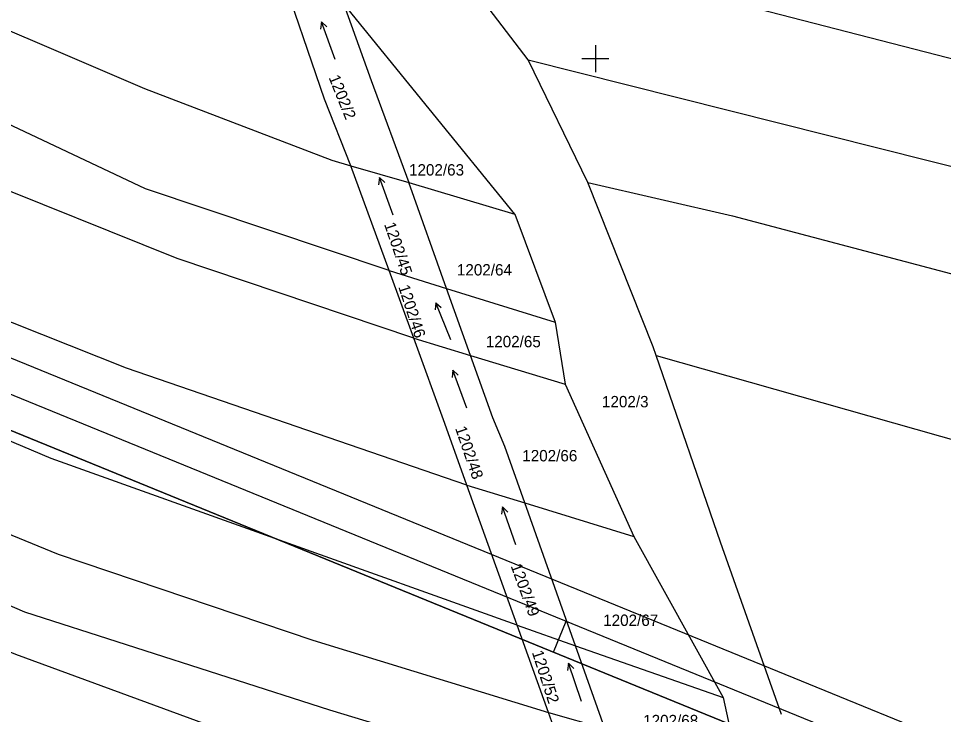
# Model space of a CAD drawing. Extents: x -779302 to -774398, y -1144902 to -1142831.
# Drawn here: x -776186.1 to -776048, y -1144098 to -1143994 of the extents above; entities that cross this region are included whole.
import ezdxf

# ---------------------------------------------------------------- set-up
doc = ezdxf.new("R2010")
doc.units = 0
for name, color, linetype in [('hektosit - Vrstva 5', 7, 'Continuous'), ('Hranice parcel', 7, 'Continuous'), ('Parcelní čísla', 7, 'Continuous'), ('Vrstva 1', 7, 'Continuous'), ('Značky kultur', 7, 'Continuous')]:
    doc.layers.add(name, color=color, linetype=linetype)

msp = doc.modelspace()

# ---------------------------------------------------------------- linework, layer by layer
at = {"layer": 'hektosit - Vrstva 5'}
for p, q in [((-776100, -1143998), (-776100, -1144002)), ((-776102, -1144000), (-776098, -1144000))]:
    msp.add_line(p, q, dxfattribs=at)
at = {"layer": 'Hranice parcel'}
for p, q in [((-776110.04, -1144000.19), (-776125.72, -1143979.61)), ((-776112, -1144023.24), (-776137.59, -1143991.79)), ((-776101.12, -1144018.49), (-776110.04, -1144000.19)), ((-776136.5, -1144016), (-776127.87, -1144018.5)), ((-776130.8, -1144031.65), (-776136.5, -1144016)), ((-776127.87, -1144018.5), (-776112, -1144023.24)), ((-776122.22, -1144034.32), (-776127.87, -1144018.5)), ((-776112, -1144023.24), (-776106.01, -1144039.37)), ((-776127.12, -1144041.75), (-776130.8, -1144031.65)), ((-776130.8, -1144031.65), (-776122.22, -1144034.32)), ((-776118.65, -1144044.33), (-776122.22, -1144034.32)), ((-776122.22, -1144034.32), (-776106.01, -1144039.37)), ((-776106.01, -1144039.37), (-776104.49, -1144048.64)), ((-776127.12, -1144041.75), (-776118.65, -1144044.33)), ((-776118.65, -1144044.33), (-776104.49, -1144048.64)), ((-776104.49, -1144048.64), (-776094.23, -1144071.36)), ((-776111.68, -1144084.62), (-776119.18, -1144063.71)), ((-776119.18, -1144063.71), (-776110.52, -1144066.36)), ((-776102.95, -1144087.69), (-776110.52, -1144066.36)), ((-776110.52, -1144066.36), (-776094.23, -1144071.36)), ((-776094.23, -1144071.36), (-776080.9, -1144095.44)), ((-776107.01, -1144097.64), (-776111.68, -1144084.62)), ((-776111.68, -1144084.62), (-776102.95, -1144087.69)), ((-776098.57, -1144100.04), (-776102.95, -1144087.69)), ((-776102.95, -1144087.69), (-776080.9, -1144095.44)), ((-776080.9, -1144095.44), (-776078.68, -1144105.69)), ((-776103.17, -1144108.34), (-776107.01, -1144097.64)), ((-776107.01, -1144097.64), (-776098.57, -1144100.04))]:
    msp.add_line(p, q, dxfattribs=at)
for points in [[(-776130.8, -1144031.65), (-776167.18, -1144019.46), (-776296.05, -1143958.5), (-776332.97, -1143941.86), (-776361.98, -1143930.46), (-776408.9, -1143915.72), (-776494.43, -1143891.48), (-776517.13, -1143883.53)], [(-776127.12, -1144041.75), (-776162.43, -1144029.85), (-776192.7, -1144017.69), (-776241.68, -1143994.5), (-776321.54, -1143955.7), (-776383.3, -1143931.9), (-776418.7, -1143920.93), (-776489.84, -1143902.44), (-776518.46, -1143894.36), (-776535.81, -1143887.79)], [(-776119.18, -1144063.71), (-776170, -1144046.22), (-776237.87, -1144019.26), (-776326.2, -1143972.4), (-776378, -1143951.65), (-776436.08, -1143933.84), (-776517.12, -1143911.82), (-776566.02, -1143893.46)], [(-776111.68, -1144084.62), (-776181.26, -1144059.74), (-776246.74, -1144031.99), (-776297.59, -1144005.18), (-776341.39, -1143983.08), (-776381.58, -1143964.67), (-776441.43, -1143945.4), (-776519.5, -1143926.07), (-776584.9, -1143900.82)], [(-776593.79, -1143913.81), (-776553, -1143929.07), (-776527.51, -1143937.51), (-776470.29, -1143952.19), (-776437.66, -1143960.66), (-776390.42, -1143976.01), (-776344.1, -1143996.17), (-776221.27, -1144057.17), (-776180.2, -1144074), (-776142.2, -1144086.85), (-776107.01, -1144097.64)], [(-776360.45, -1143916.55), (-776326.79, -1143929.74), (-776297.56, -1143943.4), (-776248.62, -1143967.36), (-776202.79, -1143989.23), (-776167.32, -1144004.47), (-776139.33, -1144015.17), (-776136.5, -1144016)], [(-776103.17, -1144108.34), (-776139.62, -1144097.29), (-776185.19, -1144082.67), (-776230.28, -1144063.14), (-776268.85, -1144045.98), (-776311.69, -1144022.93), (-776347.15, -1144004.12), (-776382.3, -1143988.84), (-776427.82, -1143973.66), (-776507.88, -1143951.31), (-776536.14, -1143944), (-776596.43, -1143923.1)], [(-776098.85, -1144120.12), (-776143.82, -1144104.66), (-776186.51, -1144088.97), (-776252.37, -1144061.74), (-776287.1, -1144045.07), (-776351.09, -1144013.34), (-776382, -1143998.69), (-776410.54, -1143987.67), (-776454.04, -1143974.87), (-776495.11, -1143963.98), (-776524.93, -1143955.67), (-776598.61, -1143932.15)], [(-776125.72, -1143979.61), (-775989.03, -1144014.87), (-775874.86, -1144045.2)], [(-776136.5, -1144016), (-776140.42, -1144006.05), (-776147.38, -1143985.8)], [(-776137.59, -1143991.79), (-776133.49, -1144003.28), (-776127.87, -1144018.5)], [(-776110.04, -1144000.19), (-776005.41, -1144026.5), (-775880.93, -1144059.24)], [(-776090.92, -1144044.35), (-776091.37, -1144043.03), (-776101.12, -1144018.49)], [(-776101.12, -1144018.49), (-776079.54, -1144023.47), (-776021.21, -1144038.9), (-775887.88, -1144074.73)], [(-776119.18, -1144063.71), (-776122.49, -1144054.47), (-776127.12, -1144041.75)], [(-776110.52, -1144066.36), (-776113.52, -1144057.92), (-776115.32, -1144053.65), (-776118.65, -1144044.33)], [(-776072.19, -1144097.96), (-776081.33, -1144072.23), (-776090.92, -1144044.35)], [(-776090.92, -1144044.35), (-776030.76, -1144061.4), (-775899.17, -1144097.95)]]:
    msp.add_lwpolyline(points, dxfattribs=at)
at = {"layer": 'Vrstva 1'}
msp.add_line((-776106.23, -1144088.65), (-776104.34, -1144084.02), dxfattribs=at)
for points in [[(-775713.68, -1144238.31), (-776879.99, -1143761.57), (-776992.36, -1144036.48), (-775826.05, -1144513.22)], [(-775828.78, -1144506.7), (-776985.84, -1144033.74), (-776877.25, -1143768.09), (-775720.2, -1144241.05)], [(-775726.71, -1144243.78), (-776684.76, -1143852.17), (-776789.57, -1144108.58), (-775831.52, -1144500.19)], [(-775831.52, -1144500.19), (-776789.57, -1144108.58), (-776684.76, -1143852.17), (-775726.71, -1144243.78)]]:
    msp.add_lwpolyline(points, close=True, dxfattribs=at)
at = {"layer": 'Značky kultur'}
for p, q in [((-776140.88, -1143994.49), (-776141.02, -1143995.58)), ((-776138.83, -1144000.13), (-776140.88, -1143994.49)), ((-776140.88, -1143994.49), (-776140.08, -1143995.24)), ((-776132.23, -1144017.75), (-776132.37, -1144018.84)), ((-776130.18, -1144023.39), (-776132.23, -1144017.75)), ((-776132.23, -1144017.75), (-776131.43, -1144018.5)), ((-776123.84, -1144036.45), (-776123.94, -1144037.54)), ((-776121.59, -1144042.01), (-776123.84, -1144036.45)), ((-776123.84, -1144036.45), (-776123.01, -1144037.17)), ((-776121.26, -1144046.55), (-776121.4, -1144047.64)), ((-776119.21, -1144052.19), (-776121.26, -1144046.55)), ((-776121.26, -1144046.55), (-776120.46, -1144047.3)), ((-776113.84, -1144066.95), (-776114, -1144068.04)), ((-776111.89, -1144072.63), (-776113.84, -1144066.95)), ((-776113.84, -1144066.95), (-776113.05, -1144067.72)), ((-776104.02, -1144090.31), (-776104.18, -1144091.4)), ((-776102.07, -1144095.99), (-776104.02, -1144090.31)), ((-776104.02, -1144090.31), (-776103.23, -1144091.07))]:
    msp.add_line(p, q, dxfattribs=at)

# ---------------------------------------------------------------- texts
at = {"layer": 'Parcelní čísla'}
for s, rotation, p in [('1202/2', 292, (-776139.85, -1144002.82)), ('1202/45', 289, (-776131.56, -1144024.75)), ('1202/46', 288, (-776129.44, -1144034.07)), ('1202/48', 289, (-776120.96, -1144055.21)), ('1202/49', 290, (-776112.67, -1144075.76)), ('1202/52', 288, (-776109.5, -1144088.67))]:
    msp.add_text(s, height=1.7, rotation=rotation, dxfattribs=at).set_placement(p)
for s, p in [('1202/63', (-776127.82, -1144017.46)), ('1202/64', (-776120.67, -1144032.39)), ('1202/65', (-776116.36, -1144043.11)), ('1202/3', (-776099.01, -1144052.08)), ('1202/66', (-776110.91, -1144060.15)), ('1202/67', (-776098.83, -1144084.73)), ('1202/68', (-776092.86, -1144099.71))]:
    msp.add_text(s, height=1.7, dxfattribs=at).set_placement(p)

doc.saveas('drawing.dxf')
